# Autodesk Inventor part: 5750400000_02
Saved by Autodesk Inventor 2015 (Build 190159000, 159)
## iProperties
Created: 2020-07
Part Number: 5750400000_02
Checked By: TraceParts S.A.
Material: Generic
Catalog Web Link: www.traceparts.com
Document SubType Name: Modeling
Designer: TraceParts
Density: 1 g/cm^3
Appearance: Default
Company: TraceParts S.A.
Author: TraceParts
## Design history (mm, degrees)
feature "5750400000_02.ipt"
body "Solid1"
